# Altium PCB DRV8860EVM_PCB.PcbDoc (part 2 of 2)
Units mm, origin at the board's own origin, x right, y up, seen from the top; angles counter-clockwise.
Board outline 101 x 60 mm, 2 copper layers (Top Layer, Bottom Layer); 122 components, 87 nets, 449 pads, 90 vias.
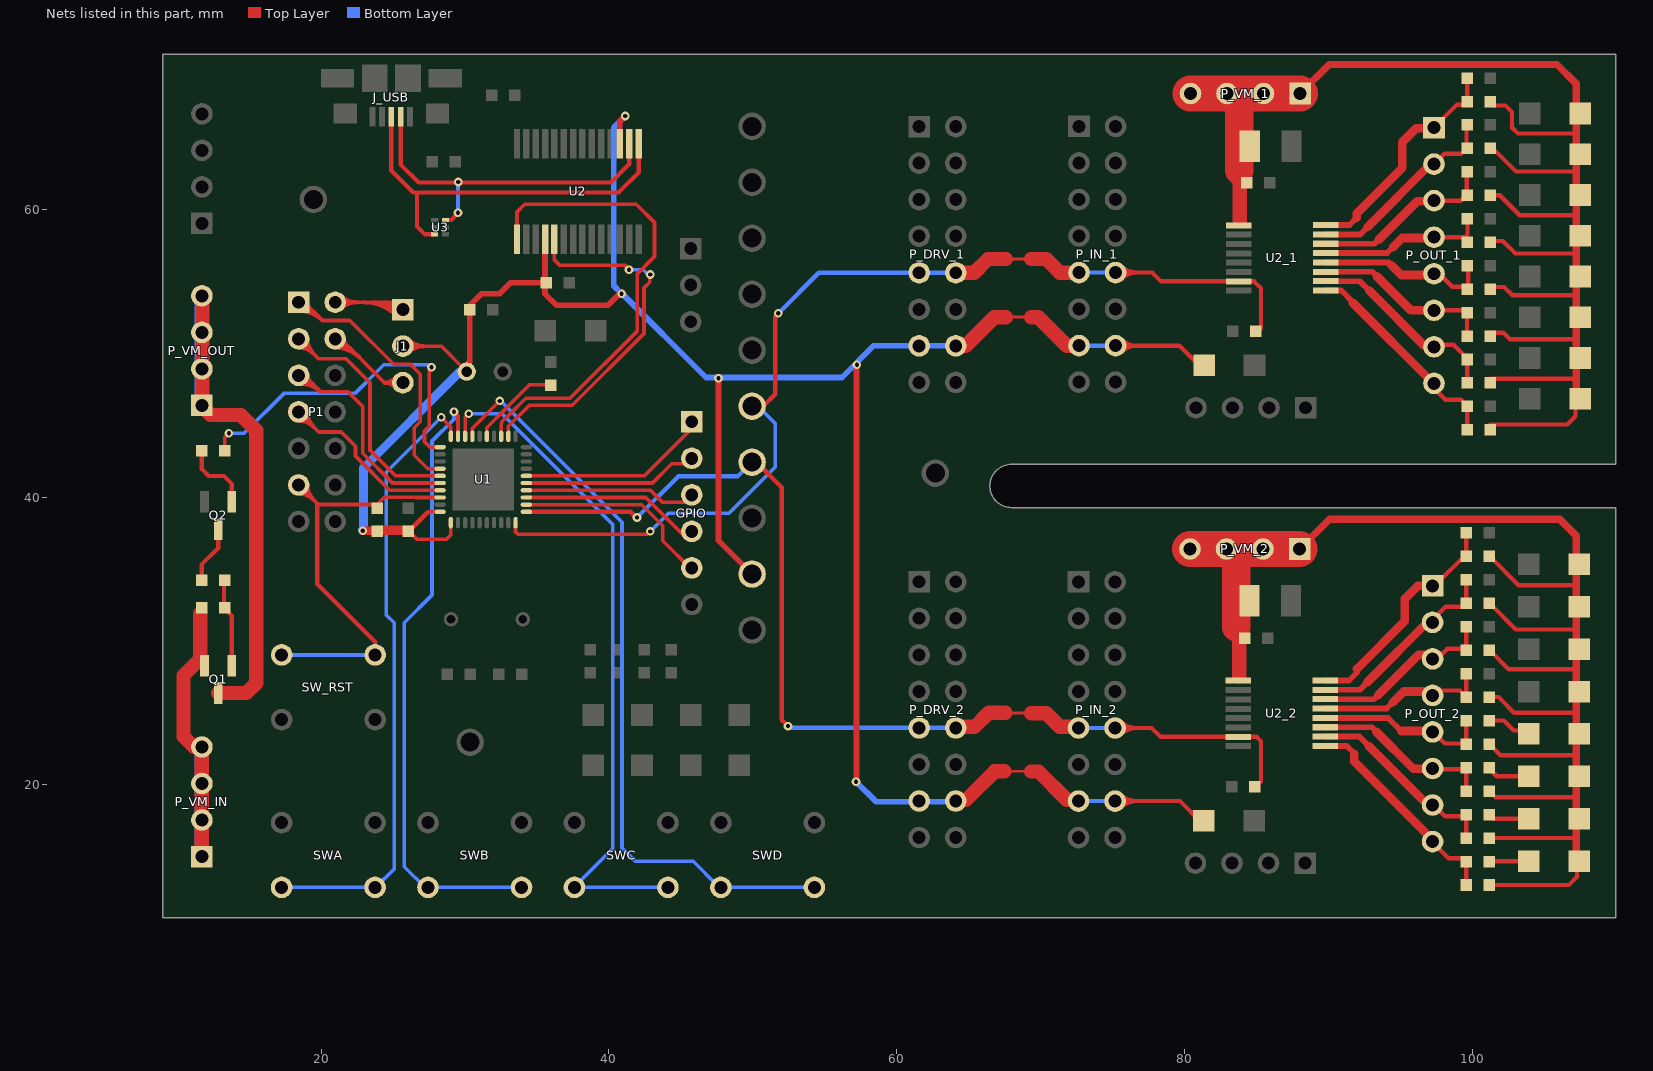
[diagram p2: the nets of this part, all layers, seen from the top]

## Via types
v1: diameter 0.6, hole 0.3, Top Layer to Bottom Layer, 90 vias

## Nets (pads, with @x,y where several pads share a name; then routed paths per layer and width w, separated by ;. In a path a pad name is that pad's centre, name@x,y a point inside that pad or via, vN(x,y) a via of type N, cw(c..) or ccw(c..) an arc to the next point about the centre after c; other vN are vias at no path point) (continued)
NetD18_2: D18.2 R19.1 | length 2.7
  Top Layer w0.3: R19.1@101.205,24.477 102.209,24.477 102.903,23.783 103.565,23.783 D18.2@103.625,23.723
NetD19_2: D19.2 R20.1 | length 2.7
  Top Layer w0.3: R20.1@101.368,20.944 101.712,20.601 D19.2@103.949,20.601
NetD20_2: D20.2 R21.1 | length 2.5
  Top Layer w0.3: R21.1@101.465,17.654 D20.2@103.949,17.654
NetD21_2: D21.2 R22.1 | length 2.6
  Top Layer w0.3: R22.1@101.361,14.708 D21.2@103.949,14.708
NetGPIO_1: GPIO.1 U1.16 | length 12.7
  Top Layer w0.254: U1.16@34.26,41.488 42.471,41.488 GPIO.1@45.653,44.67
NetGPIO_2: GPIO.2 U1.15 | length 11.9
  Top Layer w0.254: U1.15@34.26,40.988 43.027,40.988 44.373,42.334 GPIO.2@45.632,42.334
NetGPIO_3: GPIO.3 U1.14 | length 11.6
  Top Layer w0.254: U1.14@34.26,40.488 42.893,40.488 43.727,39.653 GPIO.3@45.47,39.653
NetGPIO_4: GPIO.4 U1.13 | length 12.5
  Top Layer w0.254: U1.13@34.26,39.988 42.555,39.988 45.205,37.338 GPIO.4@45.693,37.338
NetGPIO_5: GPIO.5 U1.12 | length 14.4
  Top Layer w0.254: U1.12@34.26,39.488 42.284,39.488 43.744,38.028 43.744,36.978 45.815,34.906 GPIO.5@45.815,34.535
NetJ1_1: J1.1 P1.2 | length 13
  Top Layer w0.254: P1.2@20.973,53.557 25.164,53.557 J1.1@25.672,53.049
  Top Layer w0.3: P1.2@21.397,53.133 cw(c22.421,52.108) 22.421,53.557 cw(c22.421,55.005) P1.2@21.397,53.981 ; 22.997,53.557 cw(c22.997,50.374) J1.1@25.247,52.625 ; 23.721,53.557 cw(c23.721,51.098) J1.1@25.459,52.837 ; 24.445,53.557 cw(c24.445,51.822) J1.1@25.672,53.049
NetJ1_3: J1.3 P1.4 | length 11.4
  Top Layer w0.254: P1.4@20.973,51.017 21.354,51.017 24.402,47.969 J1.3@25.672,47.969
  Top Layer w0.3: P1.4@20.973,50.417 cw(c20.973,48.048) 22.647,49.723 ; P1.4@20.973,50.717 cw(c20.973,49.073) 22.135,50.235 ; P1.4@21.573,51.017 ccw(c22.101,51.017) 21.727,50.643 ; J1.3@25.208,47.588 ccw(c24.402,46.925) 24.402,47.969 ccw(c24.402,49.013) J1.3@25.208,48.35
NetP1_1: P1.1 U1.34 | length 22
  Top Layer w0.254: P1.1@18.433,53.557 18.814,53.557 20.084,52.287 21.989,52.287 25.037,49.239 26.199,49.239 26.884,48.554 26.884,45.244 26.47,44.83 26.47,42.93 27.412,41.988 U1.34@28.26,41.988
  Top Layer w0.3: P1.1@18.436,53.257 cw(c18.454,51.665) 19.58,52.791 ; P1.1@18.439,52.957 cw(c18.466,50.669) 20.084,52.287 ; P1.1@19.033,53.557 ccw(c19.561,53.557) 19.187,53.183
NetP1_3: P1.3 U1.35 | length 18.8
  Top Layer w0.254: P1.3@18.433,51.017 19.83,49.62 21.735,49.62 23.386,47.969 23.386,43.27 25.162,41.494 27.219,41.494 27.225,41.488 U1.35@28.26,41.488
  Top Layer w0.3: P1.3@18.433,50.417 cw(c18.433,48.968) 19.457,49.993 cw(c20.481,51.017) P1.3@19.033,51.017
NetP1_5: P1.5 U1.36 | length 18
  Top Layer w0.254: P1.5@18.433,48.477 18.814,48.477 19.957,47.334 21.862,47.334 22.886,46.31 22.886,43.063 24.954,40.994 27.012,40.994 27.018,40.988 U1.36@28.26,40.988
  Top Layer w0.3: P1.5@18.456,48.178 cw(c18.56,46.858) 19.496,47.794 ; P1.5@18.48,47.879 cw(c18.627,46.005) 19.957,47.334 ; P1.5@19.033,48.477 ccw(c19.561,48.477) 19.187,48.103
NetP1_7: P1.7 U1.37 | length 14.8
  Top Layer w0.254: P1.7@18.433,45.937 19.83,44.54 21.385,44.54 22.378,43.547 22.378,42.864 24.747,40.494 26.805,40.494 26.811,40.488 U1.37@28.26,40.488
  Top Layer w0.3: P1.7@18.433,45.337 cw(c18.433,43.888) 19.457,44.913 cw(c20.481,45.937) P1.7@19.033,45.937
NetP1_11: P1.11 R1.2 SW_RST.2 U1.38 | length 31.6
  Top Layer w0.254: P1.11@18.433,40.857 19.792,39.498 23.894,39.498 24.39,39.994 26.598,39.994 26.604,39.988 U1.38@28.26,39.988
  Top Layer w0.3: P1.11@18.433,40.257 cw(c18.433,38.808) 19.457,39.833 cw(c20.481,40.857) P1.11@19.033,40.857 ; 19.732,39.559 19.732,33.957 23.752,29.937 SW_RST.2@23.752,29.042
  Bottom Layer w0.3: SW_RST.2@17.252,29.042 SW_RST.2@23.752,29.042 23.767,29.042 SW_RST.2@23.791,29.066
NetP_OUT_1_1: P_OUT_1.1 R7.2 R23.1 U2_1.16 | length 16.3
  Top Layer w0.3: P_OUT_1.1@97.354,65.699 98.949,67.294 R23.1@99.859,67.294 ; R7.2@99.579,68.95 99.675,68.854 R23.1@99.675,67.374
  Top Layer w0.4: U2_1.16@89.824,58.923 91.475,58.923 91.983,59.431
  Top Layer w0.6: 91.983,59.431 91.983,59.727 95.151,62.895 95.151,64.674 96.129,65.651 P_OUT_1.1@97.308,65.651
NetP_OUT_1_2: P_OUT_1.2 R8.2 R24.1 U2_1.15 | length 13.7
  Top Layer w0.3: P_OUT_1.2@97.354,63.159 98.067,63.873 99.234,63.873 99.612,64.251 99.612,65.81 R8.2@99.646,65.843
  Top Layer w0.4: U2_1.15@89.824,58.273 92.222,58.273 92.745,58.796
  Top Layer w0.6: 92.745,58.796 P_OUT_1.2@97.19,63.241
NetP_OUT_1_3: P_OUT_1.3 R9.2 R25.1 U2_1.14 | length 13.3
  Top Layer w0.3: P_OUT_1.3@96.967,60.683 P_OUT_1.3@97.249,60.965 ; P_OUT_1.3@97.354,60.619 99.213,60.619 99.629,61.035 99.629,62.594 R9.2@99.712,62.676
  Top Layer w0.4: U2_1.14@89.824,57.623 93.223,57.623 93.507,57.907
  Top Layer w0.6: 93.507,57.907 96.183,60.584 P_OUT_1.3@97.419,60.584
NetP_OUT_1_4: P_OUT_1.4 R10.2 R26.1 U2_1.13 | length 11.8
  Top Layer w0.3: P_OUT_1.4@97.354,58.079 99.508,58.079 99.679,58.25 R10.2@99.679,59.211 ; P_OUT_1.4@97.597,58.321 P_OUT_1.4@97.787,58.13
  Top Layer w0.4: U2_1.13@89.824,56.973 94.097,56.973 94.523,57.399
  Top Layer w0.6: 94.523,57.399 95.151,58.028 P_OUT_1.4@97.596,58.028
NetP_OUT_1_5: P_OUT_1.5 R11.2 R27.1 U2_1.12 | length 12.5
  Top Layer w0.3: P_OUT_1.5@97.282,55.525 97.358,55.449 P_OUT_1.5@97.512,55.295 ; P_OUT_1.5@97.354,55.539 97.714,55.539 98.618,54.635 99.563,54.635 99.745,54.818 R11.2@99.745,56.061
  Top Layer w0.4: U2_1.12@89.824,56.323 94.202,56.323 94.396,56.129
  Top Layer w0.6: 94.396,56.129 95.076,55.449 97.358,55.449 P_OUT_1.5@97.508,55.449
NetP_OUT_1_6: P_OUT_1.6 R12.2 R28.1 U2_1.11 | length 12.4
  Top Layer w0.3: P_OUT_1.6@97.354,52.999 99.591,52.999 99.646,52.944 99.646,51.469 R28.1@99.695,51.419
  Top Layer w0.4: U2_1.11@89.824,55.673 93.074,55.673 93.38,55.367
  Top Layer w0.6: 93.38,55.367 95.743,53.004 P_OUT_1.6@97.308,53.004
NetP_OUT_1_7: P_OUT_1.7 R13.2 R29.1 U2_1.10 | length 13
  Top Layer w0.3: P_OUT_1.7@97.361,50.603 98.719,50.603 R13.2@99.675,49.647 ; R29.1@99.675,48.248 R13.2@99.675,49.647 ; R13.2@99.695,49.828 99.675,49.807 R13.2@99.675,49.647 ; R13.2@99.697,49.625 R13.2@99.675,49.647
  Top Layer w0.4: U2_1.10@89.824,55.023 92.2,55.023 92.872,54.351
  Top Layer w0.6: 92.872,54.351 P_OUT_1.7@96.682,50.541
NetP_OUT_1_8: P_OUT_1.8 R14.2 R30.1 U2_1.9 | length 14.7
  Top Layer w0.3: P_OUT_1.8@97.164,47.768 98.142,46.79 99.235,46.79 99.675,46.349 R30.1@99.675,45.06
  Top Layer w0.4: U2_1.9@89.824,54.373 90.915,54.373 91.729,53.56
  Top Layer w0.6: 91.713,53.521 P_OUT_1.8@97.428,47.806
NetP_OUT_2_1: P_OUT_2.1 R15.2 R31.1 U2_2.16 | length 15.6
  Top Layer w0.3: P_OUT_2.1@97.406,33.894 97.446,33.894 99.605,36.053 R15.2@99.605,37.54
  Top Layer w0.4: U2_2.16@89.789,27.262 91.44,27.262 91.999,27.821 91.999,28.07
  Top Layer w0.6: 91.999,28.07 95.324,31.395 95.324,32.936 96.228,33.84 P_OUT_2.1@97.084,33.84
NetP_OUT_2_2: P_OUT_2.2 R16.2 R32.1 U2_2.15 | length 13.9
  Top Layer w0.3: P_OUT_2.2@97.203,31.427 98.164,32.388 R32.1@99.727,32.388 ; R32.1@99.573,32.791 99.605,32.823 R16.2@99.605,34.274
  Top Layer w0.4: U2_2.15@89.789,26.612 92.187,26.612 92.71,27.135
  Top Layer w0.6: 92.71,27.135 97.155,31.58 P_OUT_2.2@97.138,31.58
NetP_OUT_2_3: P_OUT_2.3 R17.2 R33.1 U2_2.14 | length 12.2
  Top Layer w0.3: P_OUT_2.3@97.715,28.907 98.283,29.475 R33.1@99.727,29.475 ; R33.1@99.593,29.601 99.605,29.614 R17.2@99.605,31.009
  Top Layer w0.4: U2_2.14@89.789,25.962 93.188,25.962 93.472,26.246
  Top Layer w0.6: 93.472,26.246 96.266,29.04 P_OUT_2.3@97.099,29.04
NetP_OUT_2_4: P_OUT_2.4 R18.2 R34.1 U2_2.13 | length 12
  Top Layer w0.3: P_OUT_2.4@97.439,26.348 97.654,26.562 99.161,26.562 99.44,26.283 99.605,26.283 R34.1@99.552,26.231 ; R34.1@99.605,26.09 R18.2@99.605,27.743
  Top Layer w0.4: U2_2.13@89.789,25.312 94.062,25.312 94.488,25.738
  Top Layer w0.6: 94.488,25.738 95.25,26.5 P_OUT_2.4@97.178,26.5
NetP_OUT_2_5: P_OUT_2.5 R19.2 R35.1 U2_2.12 | length 12.2
  Top Layer w0.3: P_OUT_2.5@97.426,23.563 98.108,22.881 99.452,22.881 99.605,23.034 R19.2@99.605,24.477 ; P_OUT_2.5@97.479,23.552 P_OUT_2.5@97.576,23.649
  Top Layer w0.4: U2_2.12@89.789,24.662 94.167,24.662 95.074,23.755
  Top Layer w0.6: 95.074,23.755 P_OUT_2.5@97.493,23.755
NetP_OUT_2_6: P_OUT_2.6 R20.2 R36.1 U2_2.11 | length 13.6
  Top Layer w0.3: P_OUT_2.6@96.809,21.504 97.197,21.117 P_OUT_2.6@97.578,20.736 ; P_OUT_2.6@97.486,21.035 97.546,21.095 99.593,21.095 99.605,21.083 R36.1@99.605,19.578
  Top Layer w0.4: U2_2.11@89.789,24.012 93.039,24.012 93.345,23.706
  Top Layer w0.6: 93.345,23.706 95.934,21.117 97.197,21.117 P_OUT_2.6@97.453,21.117
NetP_OUT_2_7: P_OUT_2.7 R21.2 R37.1 U2_2.10 | length 12.8
  Top Layer w0.3: P_OUT_2.7@97.518,18.433 98.129,17.823 R21.2@99.605,17.823 ; R21.2@99.512,17.926 99.605,17.833 R21.2@99.605,17.823 ; R37.1@99.605,16.313 R21.2@99.605,17.823 ; R21.2@99.727,17.823 R21.2@99.605,17.823
  Top Layer w0.4: U2_2.10@89.789,23.362 92.165,23.362 92.837,22.69
  Top Layer w0.6: 92.837,22.69 P_OUT_2.7@96.647,18.88
NetP_OUT_2_8: P_OUT_2.8 R22.2 R38.1 U2_2.9 | length 14.9
  Top Layer w0.3: P_OUT_2.8@97.479,15.795 98.364,14.909 R22.2@99.727,14.909 ; R22.2@99.512,14.656 99.605,14.563 R38.1@99.605,13.047
  Top Layer w0.4: U2_2.9@89.789,22.712 91.291,22.712 91.821,22.182
  Top Layer w0.6: 91.821,22.182 91.821,21.622 P_OUT_2.8@97.377,16.066
NetP_VM_IN_1: P_VM_IN.1 P_VM_IN.2 P_VM_IN.3 P_VM_IN.4 Q1.2 R39.2 | length 26
  Top Layer w1: 11.578,31.893 11.578,28.76 10.428,27.61 10.428,23.367 11.151,22.643 P_VM_IN.4@11.705,22.643 ; P_VM_IN.1@11.705,15.023 P_VM_IN.2@11.705,17.563 P_VM_IN.3@11.705,20.103 11.705,22.622 P_VM_IN.4@11.816,22.732
  Bottom Layer w1: P_VM_IN.1@11.705,15.023 P_VM_IN.2@11.705,17.563 P_VM_IN.3@11.705,20.103 P_VM_IN.4@11.705,22.643
NetP_VM_OUT_1: P_VM_OUT.1 P_VM_OUT.2 P_VM_OUT.3 P_VM_OUT.4 Q1.3 | length 40.2
  Top Layer w1: P_VM_OUT.4@11.794,53.988 11.748,53.942 11.748,46.283 12.314,45.717 14.409,45.717 15.479,44.647 15.479,27.08 14.793,26.394 Q1.3@12.838,26.394
  Bottom Layer w1: P_VM_OUT.1@11.705,46.386 P_VM_OUT.2@11.705,48.926 P_VM_OUT.3@11.705,51.466 P_VM_OUT.4@11.705,54.006
NetQ1_1: Q1.1 R39.1 R41.2 | length 6.2
  Top Layer w0.3: R41.2@13.283,34.232 13.243,34.193 13.243,32.289 13.788,31.744 Q1.1@13.788,28.294
NetQ2_1: Q2.1 R40.2 | length 5
  Top Layer w0.3: R40.2@11.718,43.194 11.703,43.179 11.703,41.956 12.176,41.482 13.231,41.482 13.788,40.926 Q2.1@13.788,39.688
NetQ2_3: Q2.3 R41.1 | length 3.6
  Top Layer w0.3: R41.1@11.686,34.231 11.686,35.319 12.834,36.467 Q2.3@12.834,37.4
NetR2_2: R2.2 U1.25 | length 6.3
  Top Layer w0.254: U1.25@31.51,44.238 31.51,44.841 32.805,46.137 32.805,46.153 34.482,47.829 R2.2@35.989,47.829
NFAULT1: nFAULT1.1 P_DRV_1.9 P_DRV_1.10 P_IN_1.9 P_IN_1.10 R1_1.1 U1.10 U2_1.7 | length 74.7
  Top Layer w0.2: 67.485,56.569 69.432,56.569
  Top Layer w0.254: U1.10@33.51,38.238 33.51,37.591 33.673,37.428 42.667,37.428 v1(42.866,37.627)
  Top Layer w0.3: nFAULT1.1@50.211,46.312 50.709,46.312 51.563,47.166 51.563,52.583 v1(51.764,52.784) ; P_IN_1.10@75.219,55.621 77.759,55.621 78.372,55.008 U2_1.7@83.774,55.008 84.849,55.008 85.322,54.535 85.322,51.732 R1_1.1@85.125,51.534 ; P_IN_1.10@75.643,55.197 cw(c76.667,54.173) 76.667,55.621 cw(c76.667,57.07) P_IN_1.10@75.643,56.046
  Top Layer w1: P_DRV_1.10@64.109,55.607 65.396,55.607 66.348,56.56 67.592,56.56 ; 69.352,56.56 70.392,56.56 71.331,55.621 P_IN_1.9@72.679,55.621
  Bottom Layer w0.254: v1(42.866,37.627) 44.138,38.899 48.353,38.899 51.561,42.106 51.561,45.136 nFAULT1.1@50.095,46.601
  Bottom Layer w0.3: v1(51.764,52.784) 54.587,55.607 P_DRV_1.9@61.569,55.607 64.02,55.607 P_DRV_1.10@64.109,55.519 ; P_IN_1.9@72.768,55.705 72.851,55.621 P_IN_1.10@75.219,55.621
NFAULT2: nFAULT2.1 P_DRV_2.9 P_DRV_2.10 P_IN_2.9 P_IN_2.10 R1_2.1 U1.11 U2_2.7 | length 76.3
  Top Layer w0.2: 67.496,24.996 69.442,24.996
  Top Layer w0.3: U1.11@34.26,38.988 41.489,38.988 41.931,38.547 41.931,38.568 v1(41.953,38.59) ; nFAULT2.1@50.269,42.433 52.013,40.69 52.013,24.526 v1(52.444,24.095) ; P_IN_2.10@75.184,23.96 77.724,23.96 78.337,23.347 U2_2.7@83.739,23.347 85.011,23.347 85.327,23.031 85.327,20.242 R1_2.1@84.956,19.871 ; P_IN_2.10@75.608,23.536 cw(c76.632,22.512) 76.632,23.96 cw(c76.632,25.409) P_IN_2.10@75.608,24.385
  Top Layer w1: P_DRV_2.10@64.119,24.035 65.406,24.035 66.397,25.026 67.539,25.026 ; 69.363,24.988 70.403,24.988 71.342,24.049 P_IN_2.9@72.689,24.049
  Bottom Layer w0.3: v1(41.953,38.59) 44.813,41.451 48.94,41.451 nFAULT2.1@49.901,42.412 ; v1(52.444,24.095) 52.57,23.969 P_DRV_2.9@61.569,23.969 63.929,23.969 P_DRV_2.10@63.941,23.98 ; P_DRV_2.10@64.031,24.035 P_DRV_2.10@64.119,23.947 ; P_IN_2.9@72.86,24.066 72.965,23.96 P_IN_2.10@75.184,23.96
RX: U1.22 U2.5 | length 25.6
  Top Layer w0.254: U1.22@33.01,44.238 33.01,44.931 34.478,46.399 37.454,46.399 42.433,51.378 42.433,54.545 42.834,54.946 v1@42.834,55.495 ; U2.5@36.209,57.932 36.209,56.494 36.564,56.139 41.079,56.139 v1(41.398,55.82)
  Bottom Layer w0.254: v1(41.398,55.82) 42.389,55.82 42.721,55.488 v1(42.871,55.488)
SA: SWA.2 U1.30 | length 43.1
  Top Layer w0.254: v1(28.339,45.556) 29.01,44.885 U1.30@29.01,44.238
  Bottom Layer w0.254: SWA.2@17.244,12.882 SWA.2@23.744,12.882 23.8,12.882 SWA.2@23.808,12.889 ; SWA.2@23.81,12.902 25.066,14.158 25.066,31.278 24.529,31.815 24.529,41.746 v1(28.339,45.556)
SB: SWB.2 U1.29 | length 43.5
  Top Layer w0.254: v1(29.228,45.937) 29.51,45.655 U1.29@29.51,44.238
  Bottom Layer w0.254: SWB.2@27.291,12.799 25.767,14.323 25.767,31.278 27.704,33.215 27.704,43.905 29.228,45.429 v1(29.228,45.937) ; SWB.2@27.423,12.882 33.857,12.882 SWB.2@33.914,12.938
SC: SWC.2 U1.28 | length 47.9
  Top Layer w0.254: U1.28@30.01,44.238 30.01,45.576 v1(30.244,45.81)
  Bottom Layer w0.254: v1(30.244,45.81) 32.565,45.81 40.277,38.098 40.277,15.61 SWC.2@37.46,12.794 ; SWC.2@37.602,12.882 SWC.2@44.102,12.882 44.128,12.882 SWC.2@44.168,12.922
SD: SWD.2 U1.27 | length 52.2
  Top Layer w0.254: U1.27@30.51,44.238 30.51,44.806 32.276,46.572 32.403,46.572 v1(32.403,46.699)
  Bottom Layer w0.254: v1(32.403,46.699) 32.403,46.572 32.594,46.572 40.912,38.255 40.912,15.62 41.84,14.692 45.854,14.692 SWD.2@47.533,13.013 ; SWD.2@47.78,12.882 54.201,12.882 SWD.2@54.225,12.906
TX: U1.23 U2.1 | length 33.9
  Top Layer w0.254: U1.23@32.51,44.238 32.51,45.155 32.556,45.201 32.556,45.245 32.994,45.683 33.02,45.683 34.223,46.886 37.299,46.886 41.979,51.566 41.979,55.422 ; U2.1@33.609,57.932 33.609,59.826 34.151,60.368 41.898,60.368 43.168,59.098 43.168,56.734 41.979,55.545 41.979,54.787
USBDM: J_USB.2 U2.16 U3.6 | length 24.1
  Top Layer w0.3: J_USB.2@25.52,66.455 25.52,63.14 26.772,61.888 40.142,61.888 41.402,63.147 U2.16@41.402,63.817 ; U3.6@28.645,59.276 29.043,59.276 29.479,59.713 29.479,59.751 v1(29.508,59.78)
  Bottom Layer w0.3: v1(29.508,59.78) 29.508,61.904 v1(29.518,61.914)
USBDP: J_USB.3 U2.15 U3.3 | length 27.5
  Top Layer w0.254: U2.15@42.025,64.616 U2.15@42.059,64.582
  Top Layer w0.3: J_USB.3@24.87,66.455 24.87,62.719 26.403,61.186 40.671,61.186 42.069,62.584 42.069,64.078 U2.15@42.153,64.162 ; 26.663,61.126 26.663,58.829 27.216,58.276 U3.3@27.875,58.276
V3P3: C1.2 C3.1 C4.2 C5.1 D1_1.1 D1_2.1 J1.2 P_DRV_1.13 P_DRV_1.14 P_DRV_2.13 P_DRV_2.14 P_IN_1.13 P_IN_1.14 P_IN_2.13 P_IN_2.14 R1.1 U1.1 U1.40 U2.4 U2.17 V3P3.1 | length 214.8
  Top Layer w0.2: 67.394,52.525 69.34,52.525 ; 67.404,20.952 69.351,20.952
  Top Layer w0.254: v1(22.878,37.682) 22.916,37.644 C4.2@26.053,37.644 26.089,37.68 C4.2@26.307,37.898 ; R1.1@23.894,37.898 C4.2@26.307,37.898 ; J1.2@25.672,50.509 28.339,50.509 C3.1@30.117,48.731 ; C4.2@26.096,37.629 26.631,37.094 28.729,37.094 29.01,37.374 U1.1@29.01,38.238 ; U1.40@28.26,38.988 27.486,38.988 27.436,38.938 ; C5.1@30.117,52.833 C5.1@30.333,53.049 30.333,53.265 31.223,54.155 31.26,54.192 32.449,54.192 32.469,54.192 33.184,54.907 33.198,54.921 33.189,54.929 C1.2@35.653,54.929 ; C1.2@35.559,54.985 35.559,55.072 C1.2@35.559,55.197 ; C4.2@26.307,37.898 26.396,37.898 27.436,38.938 ; C4.2@26.307,37.898 27.347,38.938 27.436,38.938
  Top Layer w0.3: J1.2@26.096,50.085 cw(c27.12,49.06) 27.12,50.509 cw(c27.12,51.957) J1.2@26.096,50.933 ; P_IN_2.13@72.644,18.88 P_IN_2.13@72.659,18.895 ; P_IN_1.14@75.219,50.541 79.652,50.541 D1_1.1@81.126,49.068 ; P_IN_2.14@75.608,18.456 cw(c76.632,17.432) 76.632,18.88 cw(c76.632,20.329) P_IN_2.14@75.608,19.305 ; P_IN_1.14@75.643,50.117 cw(c76.667,49.093) 76.667,50.541 cw(c76.667,51.99) P_IN_1.14@75.643,50.966 ; 76.32,18.84 76.362,18.881 79.693,18.881 D1_2.1@81.137,17.437
  Top Layer w0.4: C3.1@30.141,49.24 30.321,49.419 C5.1@30.321,53.037 ; C5.1@30.141,52.858 30.141,53.154 31.142,54.155 31.223,54.155 32.412,54.155 32.449,54.192 33.164,54.907 33.184,54.907 C1.2@35.637,54.907 ; C1.2@35.559,55.072 C1.2@35.654,54.977 ; U2.4@35.559,57.932 35.559,54.14 36.346,53.353 39.939,53.353 v1@40.875,54.289 ; U2.17@40.756,65.358 40.756,66.133 v1(41.127,66.504) ; v1(47.613,48.278) 47.613,36.997 V3P3.1@49.953,34.657 ; v1@57.21,20.17 57.21,49.188 v1(57.239,49.216)
  Top Layer w0.6: v1(22.878,37.682) 26.087,37.682 26.089,37.68 C4.2@26.137,37.632
  Top Layer w1: P_DRV_1.14@64.109,50.527 64.815,50.527 66.796,52.509 67.592,52.509 ; P_DRV_2.14@64.119,18.955 64.825,18.955 66.832,20.962 67.478,20.962 ; 69.352,52.509 69.851,52.509 71.819,50.541 P_IN_1.13@72.679,50.541 ; 69.363,20.936 69.862,20.936 71.829,18.969 P_IN_2.13@72.689,18.969
  Bottom Layer w0.254: v1(22.878,37.682) 22.878,37.741 22.878,42 29.609,48.731 29.632,48.731 C3.1@30.117,48.731
  Bottom Layer w0.3: P_IN_2.13@72.644,18.88 75.166,18.88 P_IN_2.14@75.25,18.965 ; P_IN_1.13@72.678,50.372 72.848,50.541 P_IN_1.14@75.219,50.541
  Bottom Layer w0.4: v1@40.859,54.225 46.757,48.328 56.2,48.328 58.399,50.527 P_DRV_1.13@61.569,50.527 P_DRV_1.14@64.109,50.527 64.216,50.527 P_DRV_1.14@64.327,50.416 ; v1(40.878,54.159) 40.334,54.702 40.334,65.711 41.079,66.456 v1(41.127,66.504) ; v1(57.178,20.23) 58.581,18.827 P_DRV_2.14@63.974,18.827 ; P_DRV_2.14@64.119,18.955 64.227,18.955 P_DRV_2.14@64.338,18.844
  Bottom Layer w0.6: v1@22.864,37.728 22.878,37.741 22.936,37.8 22.936,42.035 C3.1@29.632,48.731
VM1: C1_1.1 C2_1.1 D6.1 D7.1 D8.1 D9.1 D10.1 D11.1 D12.1 D13.1 P_VM_1.1 P_VM_1.2 P_VM_1.3 P_VM_1.4 R23.2 R24.2 R25.2 R26.2 R27.2 R28.2 R29.2 R30.2 U2_1.1 | length 116.4
  Top Layer w0.3: R30.2@101.275,45.06 106.616,45.06 107.189,45.633 107.189,46.528 D13.1@107.289,46.628 ; R29.2@101.275,48.248 107.168,48.248 107.245,48.325 107.255,48.335 ; R28.2@101.275,51.436 102.182,51.436 102.63,50.988 107.123,50.988 107.189,51.054 ; R27.2@101.275,54.623 102.228,54.623 102.812,54.039 107.106,54.039 107.239,53.906 ; R26.2@101.275,57.811 102.14,57.811 103.011,56.94 107.173,56.94 ; R25.2@101.275,60.999 101.92,60.999 103.31,59.609 107.206,59.609 ; R24.2@101.275,64.187 101.521,64.187 103.064,62.643 107.139,62.643 107.173,62.61 ; R23.2@101.275,67.374 101.42,67.229 102.315,67.229 102.778,66.766 102.778,65.751 102.756,65.729 103.198,65.287 107.126,65.287
  Top Layer w0.5: P_VM_1.1@88.046,68.067 90.067,70.089 105.904,70.089 107.245,68.748 107.245,48.325 107.245,47.305 D13.1@107.475,47.074
  Top Layer w1: 83.855,59.214 83.855,67.629
  Top Layer w2: P_VM_1.3@82.966,68.067 83.814,67.219 83.814,62.712
  Top Layer w2.5: P_VM_1.4@80.426,68.067 P_VM_1.3@82.966,68.067 P_VM_1.2@85.506,68.067 P_VM_1.1@88.046,68.067
VM2: C1_2.1 C2_2.1 D14.1 D15.1 D16.1 D17.1 D18.1 D19.1 D20.1 D21.1 P_VM_2.1 P_VM_2.2 P_VM_2.3 P_VM_2.4 R31.2 R32.2 R33.2 R34.2 R35.2 R36.2 R37.2 R38.2 U2_2.1 | length 117.3
  Top Layer w0.3: R38.2@101.205,13.047 106.73,13.047 107.316,13.632 107.296,13.653 D21.1@107.296,14.495 ; R37.2@101.205,16.313 107.208,16.313 107.216,16.321 ; R36.2@101.205,19.578 101.634,19.149 107.115,19.149 ; R35.2@101.205,22.844 101.991,22.058 107.244,22.058 107.256,22.058 ; R34.2@101.205,26.11 101.84,26.11 102.923,25.027 107.156,25.027 107.176,25.047 ; R33.2@101.205,29.376 102.545,28.036 107.216,28.036 ; R32.2@101.205,32.642 103.042,30.805 107.156,30.805 ; R31.2@101.205,35.907 103.219,33.894 107.244,33.894 107.316,33.894
  Top Layer w0.5: P_VM_2.1@88.011,36.406 90.082,38.477 106.097,38.477 107.244,37.33 107.244,33.894 107.244,22.058 107.244,14.692 D21.1@107.323,14.614
  Top Layer w1: 83.82,27.545 83.82,35.821
  Top Layer w2: P_VM_2.3@82.931,36.406 83.612,35.725 83.612,30.972
  Top Layer w2.5: P_VM_2.4@80.391,36.406 P_VM_2.3@82.931,36.406 P_VM_2.2@85.471,36.406 P_VM_2.1@88.011,36.406
VM_CTRL: R40.1 U1.31 | length 23.9
  Top Layer w0.254: R40.1@13.287,43.392 13.287,44.151 v1(13.583,44.447) ; v1(27.661,49.035) 27.513,48.887 27.513,44.946 27.18,44.613 27.18,43.855 27.547,43.488 U1.31@28.26,43.488
  Bottom Layer w0.254: v1(13.583,44.447) 14.637,44.447 17.412,47.222 22.351,47.222 24.349,49.22 27.476,49.22 v1(27.661,49.035)
pads on no net: J_USB.4 P1.6 P1.8 P1.10 P1.12 P1.13 P1.14 U1.8 U1.17 U1.24 U1.26 U1.32 U1.33 U2.2 U2.3 U2.6 U2.8 U2.9 U2.10 U2.11 U2.12 U2.13 U2.14 U2.19 U2.22 U2.23 U2.24 U2.27 U2.28 U3.2 U3.5

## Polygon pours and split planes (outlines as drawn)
GND on Bottom Layer "Bottom Layer-No Net" (solid, remove dead copper, pour order 5): 7.703,10.03 7.217,10.472 7.217,71.949 7.217,72.501 9.524,74.598 10.431,75.422 64.991,75.422 64.991,75.174 66.176,74.096 66.723,73.598 66.723,10.493 66.723,8.917 65.903,8.171 8.995,8.171
GND on Bottom Layer "Bottom Layer-No Net" (solid, remove dead copper, pour order 6): 70.085,72.072 70.085,8.585 70.633,8.038 111.041,8.038 111.041,71.433 110.129,72.345 109.947,72.528 71.362,72.528
GND on Top Layer "Bottom Layer-No Net" (solid, remove dead copper, pour order 4): 7.761,9.076 7.276,9.517 7.276,70.994 7.276,71.546 9.577,73.643 10.482,74.468 64.917,74.468 64.917,74.219 66.1,73.141 66.645,72.643 66.645,9.538 66.645,7.963 65.827,7.216 9.05,7.216

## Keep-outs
Keep-Out Layer:
  circle w0.254: c68.472,11.855 r0.5
  circle w0.254: c68.472,13.878 r0.5
  circle w0.254: c68.472,15.902 r0.5
  circle w0.254: c68.472,17.925 r0.5
  circle w0.254: c68.472,19.949 r0.5
  circle w0.254: c68.472,21.972 r0.5
  circle w0.254: c68.472,23.996 r0.5
  circle w0.254: c68.472,26.02 r0.5
  circle w0.254: c68.472,28.043 r0.5
  circle w0.254: c68.472,30.067 r0.5
  circle w0.254: c68.472,32.09 r0.5
  circle w0.254: c68.472,34.114 r0.5
  circle w0.254: c68.472,36.137 r0.5
  circle w0.254: c68.472,38.161 r0.5
  circle w0.254: c68.472,69.727 r0.5
  circle w0.254: c68.472,67.701 r0.5
  circle w0.254: c68.472,65.675 r0.5
  circle w0.254: c68.472,63.65 r0.5
  circle w0.254: c68.472,61.624 r0.5
  circle w0.254: c68.472,59.599 r0.5
  circle w0.254: c68.472,57.573 r0.5
  circle w0.254: c68.472,55.547 r0.5
  circle w0.254: c68.472,53.522 r0.5
  circle w0.254: c68.472,51.496 r0.5
  circle w0.254: c68.472,49.47 r0.5
  circle w0.254: c68.472,47.445 r0.5
  circle w0.254: c68.472,45.419 r0.5
  circle w0.254: c68.472,43.394 r0.5
  circle w0.254: c68.472,23.996 r0.5
  lines w0.254: 2.979,10.787 6.979,10.787 ; 2.979,70.787 6.979,70.787 ; 4.471,12.311 4.979,10.787 ; 4.471,69.263 4.979,70.787 ; 4.725,10.787 5.233,10.787 ; 4.725,70.787 5.233,70.787 ; 4.979,35.683 4.979,10.787 ; 4.979,45.891 4.979,70.787 ; 5.487,12.311 4.979,10.787 ; 5.487,69.263 4.979,70.787 ; 8.979,4.787 8.979,8.787 ; 8.979,6.533 8.979,7.041 ; 10.503,6.279 8.979,6.787 ; 10.503,7.295 8.979,6.787 ; 53.868,6.787 8.979,6.787 ; 65.091,6.787 109.979,6.787 ; 108.455,6.279 109.979,6.787 ; 108.455,7.295 109.979,6.787 ; 109.979,3.787 109.979,8.787 ; 109.979,6.533 109.979,7.041 ; 8.979,10.787 109.979,10.787 109.979,39.287 67.979,39.287 cw(c67.979,40.787) 67.979,42.287 109.979,42.287 109.979,70.787 8.979,70.787 8.979,10.787
  text "60 (mm)" at 5.894,35.937 h1.52 r90
  text "101 (mm)" at 54.122,5.873 h1.52

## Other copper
Top Layer:
  rectangle net NetP_VM_OUT_1: 11.504,24.106 15.668,27.08

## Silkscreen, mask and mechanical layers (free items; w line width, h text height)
Top Overlay:
  drawing of 196 lines, arcs and shapes, not listed
  text "Texas Instruments DRV8860EVM" at 36.008,69.055 h0.8
  text "Rev A  08/23/2013" at 36.086,67.725 h0.8
  text "DIN" at 76.87,65.4 h0.8
  text "DIN" at 57.935,65.282 h0.8
  text "OUT1" at 92.859,65.206 h0.8
  text "1:DOUT1" at 43.54,63.454 h0.8
  text "CLK" at 76.87,62.824 h0.8
  text "CLK" at 57.802,62.795 h0.8
  text "OUT2" at 92.859,62.666 h0.8
  text "2:DOUT" at 43.54,61.691 h0.8
  text "LATCH" at 56.203,60.308 h0.8
  text "LATCH" at 76.87,60.248 h0.8
  text "DRV8860" at 85.71,60.157 h0.8
  text "OUT3" at 92.859,60.126 h0.8
  text "3:DOUT2" at 43.54,59.927 h0.8
  text "DOUT1" at 56.469,57.821 h0.8
  text "DOUT" at 76.87,57.672 h0.8
  text "OUT4" at 92.859,57.586 h0.8
  text "1" at 47.507,57.187 h0.8
  text "nFAULT1" at 54.87,55.335 h0.8
  text "nFAULT" at 76.87,55.095 h0.8
  text "OUT5" at 92.859,55.046 h0.8
  text "2" at 47.507,54.512 h0.8
  text "ENABLE" at 55.403,52.848 h0.8
  text "ENABLE" at 76.87,52.519 h0.8
  text "OUT6" at 92.859,52.506 h0.8
  text "3" at 47.507,51.838 h0.8
  text "JTAG" at 16.573,50.951 h0.8 r90
  text "V3P3" at 57.002,50.361 h0.8
  text "OUT7" at 92.859,49.966 h0.8
  text "V3P3" at 76.87,49.943 h0.8
  text "GND" at 57.802,47.874 h0.8
  text "OUT8" at 92.859,47.426 h0.8
  text "GND" at 76.87,47.366 h0.8
  text "Texas Instruments DRV8860EVM Rev A  08/23/2013" at 71.806,42.969 h0.8
  text "DIN" at 76.812,33.866 h0.8
  text "DOUT1" at 56.503,33.642 h0.8
  text "OUT1" at 92.737,33.504 h0.8
  text "CLK" at 76.812,31.289 h0.8
  text "CLK" at 57.836,31.131 h0.8
  text "OUT2" at 92.737,30.964 h0.8
  text "LATCH" at 76.812,28.713 h0.8
  text "LATCH" at 56.236,28.62 h0.8
  text "DRV8860" at 85.757,28.531 h0.8
  text "OUT3" at 92.737,28.424 h0.8
  text "DOUT" at 76.812,26.137 h0.8
  text "DOUT2" at 56.236,26.109 h0.8
  text "OUT4" at 92.737,25.884 h0.8
  text "nFAULT2" at 54.637,23.598 h0.8
  text "nFAULT" at 76.812,23.561 h0.8
  text "OUT5" at 92.737,23.344 h0.8
  text "ENABLE" at 55.436,21.087 h0.8
  text "ENABLE" at 76.807,20.952 h0.8
  text "OUT6" at 92.737,20.804 h0.8
  text "V3P3" at 57.036,18.576 h0.8
  text "V3P3" at 76.812,18.408 h0.8
  text "OUT7" at 92.737,18.264 h0.8
  text "GND" at 57.836,16.065 h0.8
  text "GND" at 76.812,15.832 h0.8
  text "OUT8" at 92.737,15.724 h0.8
  text "Texas Instruments DRV8860EVM Rev A  08/23/2013" at 71.271,11.351 h0.8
